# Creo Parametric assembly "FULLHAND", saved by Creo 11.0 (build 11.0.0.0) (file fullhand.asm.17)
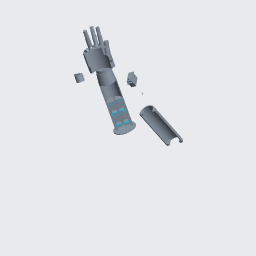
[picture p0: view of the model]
Units: Inch lbm Second (Pro/E Default); INCH, POUND, SECS

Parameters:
  MC_INTF = "11/12/2024 317"

Created from: XX_INLBS_ASM_DESIGN_ABS.ASM

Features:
  1. datum plane "ASM_RIGHT"
  2. datum plane "ASM_TOP"
  3. datum plane "ASM_FRONT"
  4. coordinate system
  5. component "HANDPRTUPDATE"
  6. component "FINGERHINGES"
  7. component "SDP_RING_ASSEMBLY"
  8. component "WRIST_COVER"
  9. component "WRIST"
  10. component "GEAR_SMALL"
  11. component "FINGERHINGES"
  12. component "FINGERHINGES"
  13. component "FINGERHINGES"
  14. component "SDP_MIDDLE_ASSEMBLY"
  15. component "SDP_MIDDLE_ASSEMBLY"
  16. component "BACK_SHELL"
  17. component "BRASS_INSERT"
  18. component "ASM0001"
  19. component "SERVO_BLACKBOX"
  20. component "THUMBHINGE"
  21. component "SDP_THUMB_ASSEMBLY"
  22. component "HINGEPIN"
  23. component "HINGEPIN"
  24. component "HINGEPIN"
  25. component "HINGEPIN"

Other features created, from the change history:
  component "HANDPRTUPDATE.PRT"
  component "SDP_MIDDLE_ASSEMBLY.ASM"
  component "SDP_THUMB_ASSEMBLY.ASM"
  component "ASM0001.ASM"
  component "FINGERHINGES.PRT"
  component "HINGEPIN.PRT"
